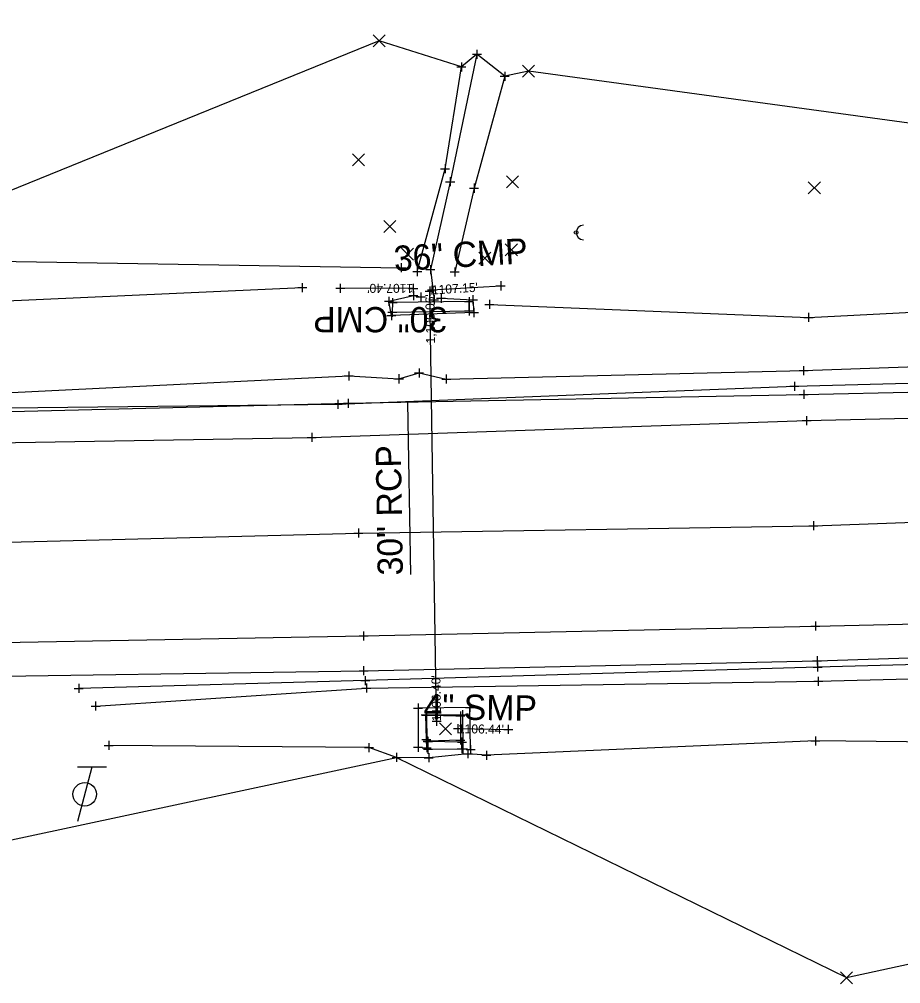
# Model space of a CAD drawing. Extents: x 2402028 to 2407435, y 498611 to 499105.
# Drawn here: x 2402751.9 to 2402849.5, y 498611 to 498717.9 of the extents above; entities that cross this region are included whole.
import ezdxf

# ---------------------------------------------------------------- set-up
doc = ezdxf.new("R2010")
doc.units = 0
for name, color, linetype in [('Default', 7, 'Continuous'), ('DR_X_Ditch', 7, 'Continuous'), ('DR_X_Headwall', 7, 'Continuous'), ('DR_X_Storm_Sewer', 7, 'Continuous'), ('DR_X_Text', 7, 'Continuous'), ('PV_X_COP', 7, 'Continuous'), ('PV_X_EOP', 7, 'Continuous'), ('PV_X_Shoulder', 7, 'Continuous'), ('RD_X_GR_Lt', 7, 'Continuous'), ('RD_X_Wall', 7, 'Continuous'), ('RW_X_CL_1000_Distances', 7, 'Continuous'), ('RW_X_CL_500_Bearings', 7, 'Continuous'), ('RW_X_CL_500_Cardinal_Points', 7, 'Continuous'), ('RW_X_CL_500_Distances', 7, 'Continuous'), ('RW_X_CL_500_Stations', 7, 'Continuous'), ('SC_Scratch1', 7, 'Continuous'), ('SV_X_Break_Lines', 7, 'Continuous'), ('SV_X_Terrain_Boundary', 7, 'Continuous')]:
    doc.layers.add(name, color=color, linetype=linetype)

msp = doc.modelspace()

# ---------------------------------------------------------------- linework, layer by layer
at = {"layer": 'Default'}
for p, q in [((2402795.49, 498688.05), (2402795.49, 498688.05)), ((2402797.57, 498687.87), (2402797.57, 498687.87)), ((2402800.45, 498639.28), (2402800.45, 498639.28))]:
    msp.add_line(p, q, dxfattribs=at)
at = {"layer": 'DR_X_Ditch'}
for points in [[(2402802.55, 498713.98), (2402799.59, 498699.86), (2402797.4, 498690.13), (2402797.81, 498686.78)], [(2402290.75, 498672.96), (2402338.21, 498675.68), (2402389.11, 498675.91), (2402437.36, 498676.99), (2402487.67, 498677.83), (2402539.05, 498679.9), (2402588.14, 498679.64), (2402639.05, 498680.84), (2402688.69, 498683.54), (2402739.78, 498686.18), (2402783.2, 498688.14)]]:
    msp.add_lwpolyline(points, dxfattribs=at)
at = {"layer": 'DR_X_Headwall'}
msp.add_lwpolyline([(2402793.22, 498686.48), (2402793.18, 498685.4), (2402801.68, 498685.55), (2402801.69, 498686.58)], close=True, dxfattribs=at)
at = {"layer": 'DR_X_Storm_Sewer'}
for p, q in [((2402797.57, 498687.87), (2402805.19, 498688.33)), ((2402795.49, 498688.05), (2402787.42, 498688.06)), ((2402798.09, 498640.1), (2402797.32, 498687.74)), ((2402800.45, 498639.28), (2402806.02, 498639.2))]:
    msp.add_line(p, q, dxfattribs=at)
at = {"layer": 'DR_X_Text'}
msp.add_line((2402794.87, 498675.42), (2402795.18, 498656.34), dxfattribs=at)
at = {"layer": 'PV_X_COP'}
msp.add_lwpolyline([(2402290.78, 498650.6), (2402340.95, 498651.54), (2402390.57, 498652.34), (2402439.7, 498652.49), (2402489.93, 498654.64), (2402539.81, 498655.53), (2402589.95, 498657.15), (2402640.38, 498659.77), (2402689.17, 498658.83), (2402739.11, 498659.65), (2402789.43, 498660.95), (2402839.82, 498661.75), (2402889.36, 498663.57), (2402939.81, 498664.58), (2402990.03, 498665.92), (2403038.83, 498667.68), (2403088.96, 498668.97), (2403139.3, 498669.99), (2403188.98, 498670.93), (2403236.78, 498672.43), (2403288.95, 498673.92), (2403339.4, 498675.07), (2403388.6, 498676.54)], dxfattribs=at)
at = {"layer": 'PV_X_EOP'}
for points in [[(2402289.63, 498661.52), (2402339.86, 498662.34), (2402390.35, 498663.57), (2402439.38, 498664.47), (2402489.03, 498665.67), (2402538.63, 498666.7), (2402622.2, 498668.45), (2402639.44, 498668.97), (2402688.21, 498669.91), (2402738.3, 498670.77), (2402784.26, 498671.54), (2402839.07, 498673.4), (2402887.81, 498674.54), (2402939.07, 498675.44), (2402989.96, 498676.81), (2403039.49, 498677.82), (2403088.59, 498679.54), (2403138.58, 498681), (2403188.48, 498682.36), (2403236.31, 498683.8), (2403287.8, 498685.14), (2403338.61, 498686.54), (2403387.34, 498688.53)], [(2402290.91, 498639.29), (2402341.07, 498640.3), (2402390.61, 498641.23), (2402440.65, 498642.38), (2402490.15, 498643.23), (2402540.35, 498644.45), (2402590.8, 498645.77), (2402640.33, 498646.73), (2402690.18, 498647.64), (2402739.92, 498648.63), (2402790, 498649.56), (2402840.05, 498650.65), (2402889.89, 498651.78), (2402940.17, 498653.2), (2402989.78, 498654.87), (2403039.63, 498656.02), (2403089.54, 498657.39), (2403140.04, 498658.56), (2403189.82, 498659.81), (2403238.57, 498661.04), (2403289.76, 498662.62), (2403340.13, 498663.91), (2403389.07, 498665.43)]]:
    msp.add_lwpolyline(points, dxfattribs=at)
at = {"layer": 'PV_X_Shoulder'}
for p, q in [((2402838.76, 498676.31), (2402887.44, 498677.34)), ((2402736.61, 498674.04), (2402788.29, 498675.32)), ((2402788.29, 498675.32), (2402838.76, 498676.31))]:
    msp.add_line(p, q, dxfattribs=at)
msp.add_lwpolyline([(2402291.13, 498635.58), (2402341.06, 498636.96), (2402390.62, 498637.69), (2402440.73, 498638.55), (2402490.3, 498639.85), (2402540.78, 498641.01), (2402590.73, 498641.96), (2402640.23, 498642.72), (2402690.38, 498643.95), (2402740.06, 498644.93), (2402790, 498645.7), (2402840.23, 498646.8), (2402889.99, 498648.42), (2402940.22, 498649.59), (2402989.85, 498649.92), (2403040.06, 498650.63), (2403089.93, 498652.73), (2403140.24, 498654.26), (2403189.57, 498655.62), (2403238.67, 498657.76), (2403289.89, 498659.04), (2403340.12, 498659.5), (2403389.1, 498660.69)], dxfattribs=at)
at = {"layer": 'RD_X_GR_Lt'}
for points in [[(2402671.34, 498674.03), (2402687.6, 498674.22), (2402737.25, 498674.66), (2402787.14, 498675.21), (2402837.72, 498677.2), (2402886.73, 498678.51), (2402937.55, 498679.97), (2402988.38, 498681.88), (2403034.42, 498684.03)], [(2402983.63, 498647.12), (2402940.38, 498648.9), (2402890.36, 498647.43), (2402840.29, 498646.11), (2402790.18, 498644.6), (2402758.45, 498643.74)]]:
    msp.add_lwpolyline(points, dxfattribs=at)
at = {"layer": 'RD_X_Wall'}
for points in [[(2402801.01, 498637.04), (2402801.86, 498636.96), (2402801.78, 498641.63), (2402796.03, 498641.56), (2402796.04, 498637.23), (2402797, 498637.17), (2402796.96, 498638.07), (2402796.88, 498640.82), (2402800.97, 498640.83)], [(2402800.88, 498637.06), (2402800.9, 498637.8), (2402797.13, 498637.85), (2402797.13, 498637.01)]]:
    msp.add_lwpolyline(points, close=True, dxfattribs=at)
at = {"layer": 'RW_X_CL_1000_Distances'}
for p, q in [((2402761.51, 498635.01), (2402758.31, 498635.01)), ((2402759.91, 498635.01), (2402758.31, 498629.01))]:
    msp.add_line(p, q, dxfattribs=at)
msp.add_circle((2402759.11, 498632.01), 1.3, dxfattribs=at)
at = {"layer": 'RW_X_CL_500_Bearings'}
for p, q in [((2402802.05, 498713.98), (2402803.05, 498713.98)), ((2402802.55, 498714.48), (2402802.55, 498713.48)), ((2402802.55, 498713.98), (2402802.55, 498713.98)), ((2402800.83, 498713.08), (2402800.83, 498712.08)), ((2402800.33, 498712.58), (2402801.33, 498712.58)), ((2402800.83, 498712.58), (2402800.83, 498712.58)), ((2402805.63, 498712.05), (2402805.63, 498711.05)), ((2402805.13, 498711.55), (2402806.13, 498711.55)), ((2402805.63, 498711.55), (2402805.63, 498711.55)), ((2402798.52, 498701.3), (2402799.52, 498701.3)), ((2402799.02, 498701.8), (2402799.02, 498700.8)), ((2402799.02, 498701.3), (2402799.02, 498701.3)), ((2402799.59, 498700.36), (2402799.59, 498699.36)), ((2402799.09, 498699.86), (2402800.09, 498699.86)), ((2402799.59, 498699.86), (2402799.59, 498699.86)), ((2402801.73, 498699.15), (2402802.73, 498699.15)), ((2402802.23, 498699.65), (2402802.23, 498698.65)), ((2402802.23, 498699.15), (2402802.23, 498699.15)), ((2402793.67, 498690.34), (2402794.67, 498690.34)), ((2402794.17, 498690.84), (2402794.17, 498689.84)), ((2402794.17, 498690.34), (2402794.17, 498690.34)), ((2402795.94, 498690.42), (2402795.94, 498689.42)), ((2402797.4, 498690.63), (2402797.4, 498689.63)), ((2402800.09, 498690.38), (2402800.09, 498689.38)), ((2402795.44, 498689.92), (2402796.44, 498689.92)), ((2402795.94, 498689.92), (2402795.94, 498689.92)), ((2402796.9, 498690.13), (2402797.9, 498690.13)), ((2402797.4, 498690.13), (2402797.4, 498690.13)), ((2402799.59, 498689.88), (2402800.59, 498689.88)), ((2402800.09, 498689.88), (2402800.09, 498689.88)), ((2402782.7, 498688.14), (2402783.7, 498688.14)), ((2402783.2, 498688.64), (2402783.2, 498687.64)), ((2402783.2, 498688.14), (2402783.2, 498688.14)), ((2402792.8, 498687.13), (2402792.8, 498686.13)), ((2402795.02, 498687.25), (2402796.02, 498687.25)), ((2402795.52, 498687.75), (2402795.52, 498686.75)), ((2402795.52, 498687.25), (2402795.52, 498687.25)), ((2402795.84, 498687.1), (2402796.84, 498687.1)), ((2402796.34, 498687.6), (2402796.34, 498686.6)), ((2402796.34, 498687.1), (2402796.34, 498687.1)), ((2402797.81, 498687.28), (2402797.81, 498686.28)), ((2402798.59, 498687.45), (2402798.59, 498686.45)), ((2402801.69, 498687.08), (2402801.69, 498686.08)), ((2402802.1, 498687.29), (2402802.1, 498686.29)), ((2402792.3, 498686.63), (2402793.3, 498686.63)), ((2402792.72, 498686.48), (2402793.72, 498686.48)), ((2402792.8, 498686.63), (2402792.8, 498686.63)), ((2402793.22, 498686.98), (2402793.22, 498685.98)), ((2402793.22, 498686.48), (2402793.22, 498686.48)), ((2402797.31, 498686.78), (2402798.31, 498686.78)), ((2402797.81, 498686.78), (2402797.81, 498686.78)), ((2402798.09, 498686.95), (2402799.09, 498686.95)), ((2402798.59, 498686.95), (2402798.59, 498686.95)), ((2402801.19, 498686.58), (2402802.19, 498686.58)), ((2402801.6, 498686.79), (2402802.6, 498686.79)), ((2402801.68, 498686.05), (2402801.68, 498685.05)), ((2402801.69, 498686.58), (2402801.69, 498686.58)), ((2402802.1, 498686.79), (2402802.1, 498686.79)), ((2402803.44, 498686.28), (2402804.44, 498686.28)), ((2402803.94, 498686.78), (2402803.94, 498685.78)), ((2402803.94, 498686.28), (2402803.94, 498686.28)), ((2402792.58, 498685.04), (2402793.58, 498685.04)), ((2402792.68, 498685.4), (2402793.68, 498685.4)), ((2402793.08, 498685.54), (2402793.08, 498684.54)), ((2402793.08, 498685.04), (2402793.08, 498685.04)), ((2402793.18, 498685.9), (2402793.18, 498684.9)), ((2402793.18, 498685.4), (2402793.18, 498685.4)), ((2402801.18, 498685.55), (2402802.18, 498685.55)), ((2402801.68, 498685.55), (2402801.68, 498685.55)), ((2402801.71, 498685.36), (2402802.71, 498685.36)), ((2402802.21, 498685.86), (2402802.21, 498684.86)), ((2402802.21, 498685.36), (2402802.21, 498685.36)), ((2402839.28, 498685.34), (2402839.28, 498684.34)), ((2402838.78, 498684.84), (2402839.78, 498684.84)), ((2402839.28, 498684.84), (2402839.28, 498684.84)), ((2402788.35, 498678.85), (2402788.35, 498677.85)), ((2402793.91, 498678.53), (2402793.91, 498677.53)), ((2402795.65, 498678.69), (2402796.65, 498678.69)), ((2402796.15, 498679.19), (2402796.15, 498678.19)), ((2402796.15, 498678.69), (2402796.15, 498678.69)), ((2402838.24, 498678.94), (2402839.24, 498678.94)), ((2402838.74, 498679.44), (2402838.74, 498678.44)), ((2402838.74, 498678.94), (2402838.74, 498678.94)), ((2402787.85, 498678.35), (2402788.85, 498678.35)), ((2402788.35, 498678.35), (2402788.35, 498678.35)), ((2402793.41, 498678.03), (2402794.41, 498678.03)), ((2402793.91, 498678.03), (2402793.91, 498678.03)), ((2402798.65, 498678), (2402799.65, 498678)), ((2402799.15, 498678.5), (2402799.15, 498677.5)), ((2402799.15, 498678), (2402799.15, 498678)), ((2402837.72, 498677.7), (2402837.72, 498676.7)), ((2402837.22, 498677.2), (2402838.22, 498677.2)), ((2402837.72, 498677.2), (2402837.72, 498677.2)), ((2402838.76, 498676.81), (2402838.76, 498675.81)), ((2402787.14, 498675.71), (2402787.14, 498674.71)), ((2402787.79, 498675.32), (2402788.79, 498675.32)), ((2402788.29, 498675.82), (2402788.29, 498674.82)), ((2402788.29, 498675.32), (2402788.29, 498675.32)), ((2402838.26, 498676.31), (2402839.26, 498676.31)), ((2402838.76, 498676.31), (2402838.76, 498676.31)), ((2402786.64, 498675.21), (2402787.64, 498675.21)), ((2402787.14, 498675.21), (2402787.14, 498675.21)), ((2402838.57, 498673.4), (2402839.57, 498673.4)), ((2402839.07, 498673.9), (2402839.07, 498672.9)), ((2402839.07, 498673.4), (2402839.07, 498673.4)), ((2402783.76, 498671.54), (2402784.76, 498671.54)), ((2402784.26, 498672.04), (2402784.26, 498671.04)), ((2402784.26, 498671.54), (2402784.26, 498671.54)), ((2402789.43, 498661.45), (2402789.43, 498660.45)), ((2402839.32, 498661.75), (2402840.32, 498661.75)), ((2402839.82, 498662.25), (2402839.82, 498661.25)), ((2402839.82, 498661.75), (2402839.82, 498661.75)), ((2402788.93, 498660.95), (2402789.93, 498660.95)), ((2402789.43, 498660.95), (2402789.43, 498660.95)), ((2402840.05, 498651.15), (2402840.05, 498650.15)), ((2402790, 498650.06), (2402790, 498649.06)), ((2402839.55, 498650.65), (2402840.55, 498650.65)), ((2402840.05, 498650.65), (2402840.05, 498650.65)), ((2402789.5, 498649.56), (2402790.5, 498649.56)), ((2402790, 498649.56), (2402790, 498649.56)), ((2402839.73, 498646.8), (2402840.73, 498646.8)), ((2402840.23, 498647.3), (2402840.23, 498646.3)), ((2402840.23, 498646.8), (2402840.23, 498646.8)), ((2402840.29, 498646.61), (2402840.29, 498645.61)), ((2402789.5, 498645.7), (2402790.5, 498645.7)), ((2402790, 498646.2), (2402790, 498645.2)), ((2402790, 498645.7), (2402790, 498645.7)), ((2402839.79, 498646.11), (2402840.79, 498646.11)), ((2402840.29, 498646.11), (2402840.29, 498646.11)), ((2402789.68, 498644.6), (2402790.68, 498644.6)), ((2402790.18, 498645.1), (2402790.18, 498644.1)), ((2402790.18, 498644.6), (2402790.18, 498644.6)), ((2402839.86, 498644.53), (2402840.86, 498644.53)), ((2402840.36, 498645.03), (2402840.36, 498644.03)), ((2402840.36, 498644.53), (2402840.36, 498644.53)), ((2402757.95, 498643.74), (2402758.95, 498643.74)), ((2402758.45, 498644.24), (2402758.45, 498643.24)), ((2402758.45, 498643.74), (2402758.45, 498643.74)), ((2402789.81, 498643.78), (2402790.81, 498643.78)), ((2402790.31, 498644.28), (2402790.31, 498643.28)), ((2402790.31, 498643.78), (2402790.31, 498643.78)), ((2402760.32, 498642.29), (2402760.32, 498641.29)), ((2402759.82, 498641.79), (2402760.82, 498641.79)), ((2402760.32, 498641.79), (2402760.32, 498641.79)), ((2402795.53, 498641.56), (2402796.53, 498641.56)), ((2402796.03, 498642.06), (2402796.03, 498641.06)), ((2402796.03, 498641.56), (2402796.03, 498641.56)), ((2402796.88, 498641.32), (2402796.88, 498640.32)), ((2402796.97, 498641.27), (2402796.97, 498640.27)), ((2402800.72, 498641.19), (2402800.72, 498640.19)), ((2402800.97, 498641.33), (2402800.97, 498640.33)), ((2402801.28, 498641.63), (2402802.28, 498641.63)), ((2402801.78, 498642.13), (2402801.78, 498641.13)), ((2402801.78, 498641.63), (2402801.78, 498641.63)), ((2402796.38, 498640.82), (2402797.38, 498640.82)), ((2402796.47, 498640.77), (2402797.47, 498640.77)), ((2402796.88, 498640.82), (2402796.88, 498640.82)), ((2402796.97, 498640.77), (2402796.97, 498640.77)), ((2402800.22, 498640.69), (2402801.22, 498640.69)), ((2402800.47, 498640.83), (2402801.47, 498640.83)), ((2402800.72, 498640.69), (2402800.72, 498640.69)), ((2402800.97, 498640.83), (2402800.97, 498640.83)), ((2402761.78, 498637.93), (2402761.78, 498636.93)), ((2402796.46, 498638.07), (2402797.46, 498638.07)), ((2402796.96, 498638.57), (2402796.96, 498637.57)), ((2402796.96, 498638.07), (2402796.96, 498638.07)), ((2402797.09, 498638.41), (2402797.09, 498637.41)), ((2402797.13, 498638.35), (2402797.13, 498637.35)), ((2402800.22, 498638.02), (2402801.22, 498638.02)), ((2402800.72, 498638.52), (2402800.72, 498637.52)), ((2402800.72, 498638.02), (2402800.72, 498638.02)), ((2402800.9, 498638.3), (2402800.9, 498637.3)), ((2402840.04, 498638.43), (2402840.04, 498637.43)), ((2402761.28, 498637.43), (2402762.28, 498637.43)), ((2402761.78, 498637.43), (2402761.78, 498637.43)), ((2402790.09, 498637.18), (2402791.09, 498637.18)), ((2402790.59, 498637.68), (2402790.59, 498636.68)), ((2402790.59, 498637.18), (2402790.59, 498637.18)), ((2402795.54, 498637.23), (2402796.54, 498637.23)), ((2402796.04, 498637.73), (2402796.04, 498636.73)), ((2402796.04, 498637.23), (2402796.04, 498637.23)), ((2402796.5, 498637.17), (2402797.5, 498637.17)), ((2402796.59, 498637.91), (2402797.59, 498637.91)), ((2402796.63, 498637.85), (2402797.63, 498637.85)), ((2402796.63, 498637.01), (2402797.63, 498637.01)), ((2402797, 498637.67), (2402797, 498636.67)), ((2402797, 498637.17), (2402797, 498637.17)), ((2402797.09, 498637.91), (2402797.09, 498637.91)), ((2402797.13, 498637.85), (2402797.13, 498637.85)), ((2402797.13, 498637.51), (2402797.13, 498636.51)), ((2402797.13, 498637.01), (2402797.13, 498637.01)), ((2402800.38, 498637.06), (2402801.38, 498637.06)), ((2402800.4, 498637.8), (2402801.4, 498637.8)), ((2402800.51, 498637.04), (2402801.51, 498637.04)), ((2402800.88, 498637.56), (2402800.88, 498636.56)), ((2402800.88, 498637.06), (2402800.88, 498637.06)), ((2402800.9, 498637.8), (2402800.9, 498637.8)), ((2402801.01, 498637.54), (2402801.01, 498636.54)), ((2402801.01, 498637.04), (2402801.01, 498637.04)), ((2402801.36, 498636.96), (2402802.36, 498636.96)), ((2402801.54, 498637.01), (2402801.54, 498636.01)), ((2402801.86, 498637.46), (2402801.86, 498636.46)), ((2402801.86, 498636.96), (2402801.86, 498636.96)), ((2402839.54, 498637.93), (2402840.54, 498637.93)), ((2402840.04, 498637.93), (2402840.04, 498637.93)), ((2402793.16, 498636.1), (2402794.16, 498636.1)), ((2402793.66, 498636.6), (2402793.66, 498635.6)), ((2402793.66, 498636.1), (2402793.66, 498636.1)), ((2402796.71, 498636.06), (2402797.71, 498636.06)), ((2402797.21, 498636.56), (2402797.21, 498635.56)), ((2402797.21, 498636.06), (2402797.21, 498636.06)), ((2402801.04, 498636.51), (2402802.04, 498636.51)), ((2402801.54, 498636.51), (2402801.54, 498636.51)), ((2402803.11, 498636.34), (2402804.11, 498636.34)), ((2402803.61, 498636.84), (2402803.61, 498635.84)), ((2402803.61, 498636.34), (2402803.61, 498636.34))]:
    msp.add_line(p, q, dxfattribs=at)
at = {"layer": 'RW_X_CL_500_Cardinal_Points'}
msp.add_circle((2402813.54, 498694.24), 0.2, dxfattribs=at)
msp.add_arc((2402814.34, 498694.24), 0.8, 90, 270, dxfattribs=at)
at = {"layer": 'RW_X_CL_500_Distances'}
for p, q in [((2402787.42, 498688.56), (2402787.42, 498687.56)), ((2402795.49, 498688.55), (2402795.49, 498687.55)), ((2402797.32, 498688.24), (2402797.32, 498687.24)), ((2402797.57, 498688.37), (2402797.57, 498687.37)), ((2402804.69, 498688.33), (2402805.69, 498688.33)), ((2402805.19, 498688.83), (2402805.19, 498687.83)), ((2402805.19, 498688.33), (2402805.19, 498688.33)), ((2402786.92, 498688.06), (2402787.92, 498688.06)), ((2402787.42, 498688.06), (2402787.42, 498688.06)), ((2402794.99, 498688.05), (2402795.99, 498688.05)), ((2402795.49, 498688.05), (2402795.49, 498688.05)), ((2402796.82, 498687.74), (2402797.82, 498687.74)), ((2402797.07, 498687.87), (2402798.07, 498687.87)), ((2402797.32, 498687.74), (2402797.32, 498687.74)), ((2402797.57, 498687.87), (2402797.57, 498687.87)), ((2402797.59, 498640.1), (2402798.59, 498640.1)), ((2402798.09, 498640.6), (2402798.09, 498639.6)), ((2402798.09, 498640.1), (2402798.09, 498640.1)), ((2402799.95, 498639.28), (2402800.95, 498639.28)), ((2402800.45, 498639.78), (2402800.45, 498638.78)), ((2402800.45, 498639.28), (2402800.45, 498639.28)), ((2402805.52, 498639.2), (2402806.52, 498639.2)), ((2402806.02, 498639.7), (2402806.02, 498638.7)), ((2402806.02, 498639.2), (2402806.02, 498639.2))]:
    msp.add_line(p, q, dxfattribs=at)
at = {"layer": 'RW_X_CL_500_Stations'}
for p, q in [((2402791.07, 498714.82), (2402792.4, 498716.15)), ((2402791.07, 498716.15), (2402792.4, 498714.82)), ((2402807.59, 498711.44), (2402808.93, 498712.78)), ((2402807.59, 498712.78), (2402808.93, 498711.44)), ((2402788.76, 498701.63), (2402790.1, 498702.96)), ((2402788.76, 498702.96), (2402790.1, 498701.63)), ((2402805.82, 498699.17), (2402807.16, 498700.5)), ((2402805.82, 498700.5), (2402807.16, 498699.17)), ((2402839.26, 498698.53), (2402840.6, 498699.86)), ((2402839.26, 498699.86), (2402840.6, 498698.53)), ((2402792.23, 498694.23), (2402793.56, 498695.56)), ((2402792.23, 498695.56), (2402793.56, 498694.23)), ((2402794.19, 498691.16), (2402795.52, 498692.49)), ((2402794.19, 498692.49), (2402795.52, 498691.16)), ((2402805.7, 498691.66), (2402807.03, 498692.99)), ((2402805.7, 498692.99), (2402807.03, 498691.66)), ((2402802.75, 498690.74), (2402804.08, 498692.07)), ((2402802.75, 498692.07), (2402804.08, 498690.74)), ((2402798.41, 498638.58), (2402799.75, 498639.91)), ((2402798.41, 498639.91), (2402799.75, 498638.58)), ((2402842.81, 498611.03), (2402844.15, 498612.36)), ((2402842.81, 498612.36), (2402844.15, 498611.03))]:
    msp.add_line(p, q, dxfattribs=at)
at = {"layer": 'SV_X_Break_Lines'}
for points in [[(2402795.94, 498689.92), (2402799.02, 498701.3), (2402800.83, 498712.58)], [(2402805.63, 498711.55), (2402802.23, 498699.15), (2402800.09, 498689.88)], [(2402288.25, 498667.48), (2402339.69, 498668.17), (2402389.86, 498669.48), (2402438.42, 498670.54), (2402588.11, 498673.81), (2402638.99, 498674.42), (2402672.44, 498676.2), (2402688.28, 498675.46), (2402738.27, 498675.88), (2402788.35, 498678.35), (2402793.91, 498678.03), (2402796.15, 498678.69), (2402799.15, 498678), (2402838.74, 498678.94), (2402887.97, 498680.68), (2402923.89, 498681.63), (2402938.31, 498682.59), (2402988.84, 498684.41), (2403028.61, 498685.67), (2403039.38, 498686.37), (2403044.21, 498687.92), (2403044.42, 498694.26), (2403040.83, 498698.9), (2403035.04, 498699.28)], [(2402292.1, 498676.55), (2402340.39, 498678.44), (2402390.48, 498683.5), (2402437.19, 498682.37), (2402495.51, 498686.91), (2402536.2, 498684.54), (2402589.33, 498687.74), (2402637.4, 498686.94), (2402692.15, 498694.03), (2402740.25, 498691.21), (2402794.17, 498690.34)], [(2402803.94, 498686.28), (2402839.28, 498684.84), (2402889.48, 498687.41), (2402915.61, 498690.01)], [(2402798.59, 498686.95), (2402802.1, 498686.79), (2402802.21, 498685.36), (2402793.08, 498685.04), (2402792.8, 498686.63), (2402795.52, 498687.25), (2402796.34, 498687.1)], [(2402760.32, 498641.79), (2402790.31, 498643.78), (2402840.36, 498644.53), (2402890.67, 498645.85), (2402940.48, 498646.96), (2402971.99, 498646.28)], [(2402976.32, 498641.36), (2402940.23, 498638.5), (2402890.46, 498637.38), (2402840.04, 498637.93), (2402803.61, 498636.34), (2402801.54, 498636.51), (2402797.21, 498636.06), (2402793.66, 498636.1), (2402790.59, 498637.18), (2402761.78, 498637.43)]]:
    msp.add_lwpolyline(points, dxfattribs=at)
msp.add_lwpolyline([(2402796.97, 498640.77), (2402800.72, 498640.69), (2402800.72, 498638.02), (2402797.09, 498637.91)], close=True, dxfattribs=at)
at = {"layer": 'SV_X_Terrain_Boundary'}
for points in [[(2403390.54, 498717.85), (2403340.67, 498716.01), (2403291.04, 498712.96), (2403238.44, 498711.46), (2403188.93, 498712.35), (2403141.78, 498709.87), (2403108.52, 498702.31), (2403030.94, 498708.33), (2402991.96, 498712.04), (2402946.72, 498714.63), (2402886.9, 498701.35), (2402808.26, 498712.11), (2402805.63, 498711.55), (2402802.55, 498713.98), (2402800.83, 498712.58), (2402791.73, 498715.48), (2402739.88, 498694.44), (2402686.71, 498702.37), (2402636.92, 498697.87)], [(2402641.3, 498620.88), (2402692.24, 498622.71), (2402740.26, 498624.67), (2402793.66, 498636.1), (2402843.48, 498611.7), (2402939.98, 498632.65), (2402988.61, 498630.24), (2403041.47, 498629.99), (2403091.65, 498630.18), (2403191.21, 498636.27), (2403240.26, 498637.09), (2403290.41, 498638.6), (2403346.11, 498636.26), (2403438.36, 498646.02)]]:
    msp.add_lwpolyline(points, dxfattribs=at)

# ---------------------------------------------------------------- texts
at = {"layer": 'DR_X_Text'}
for s, rotation, p in [('36" CMP', 3.4959, (2402793.43, 498689.94)), ('36" CMP', 3.4959, (2402793.43, 498689.94)), ('30" CMP', 179.9645, (2402799.27, 498685.98)), ('30" CMP', 179.9645, (2402799.27, 498685.98)), ('30" RCP', 90.9236, (2402794.36, 498656.27)), ('4" SMP', 359.1558, (2402796.62, 498640.33))]:
    msp.add_text(s, height=2.8, rotation=rotation, dxfattribs=at).set_placement(p)
at = {"layer": 'SC_Scratch1'}
for s, rotation, p in [("1107.40'", 179.9645, (2402795.49, 498688.55)), ("1107.15'", 3.4959, (2402797.6, 498687.37)), ("1,106.06'", 90.9236, (2402797.92, 498681.95)), ("1106.40'", 90.9236, (2402798.59, 498640.11)), ("1106.44'", 359.1558, (2402800.44, 498638.78))]:
    msp.add_text(s, height=1, rotation=rotation, dxfattribs=at).set_placement(p)

doc.saveas('drawing.dxf')
